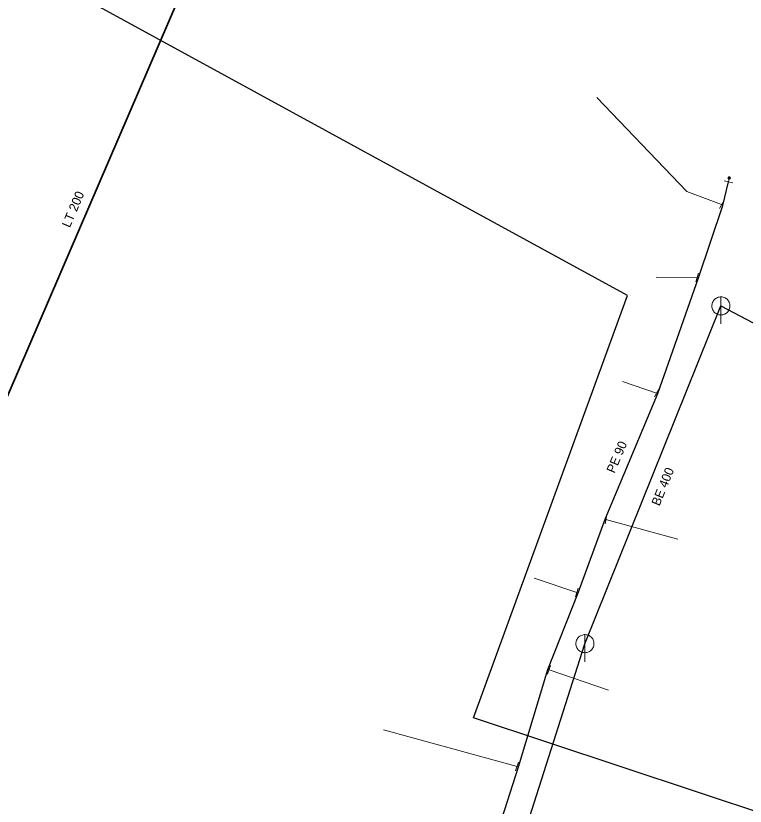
# Model space of a CAD drawing. Extents: x -659250 to -657316, y -997555 to -993684.
# Drawn here: x -658626.7 to -658546, y -994093.6 to -994006.2 of the extents above; entities that cross this region are included whole.
import ezdxf

# ---------------------------------------------------------------- set-up
doc = ezdxf.new("R2010")
doc.units = 0
doc.header["$LTSCALE"] = 0.4
doc.layers.add('1', color=7, linetype='Continuous')
for name, color, linetype, lineweight in [('13', 7, 'Continuous', 13), ('14', 7, 'Continuous', 25), ('17', 7, 'Continuous', 25), ('22', 7, 'Continuous', 13), ('34', 7, 'Continuous', 13), ('9', 7, 'Continuous', 13)]:
    doc.layers.add(name, color=color, linetype=linetype, lineweight=lineweight)

msp = doc.modelspace()

# ---------------------------------------------------------------- linework, layer by layer
at = {"layer": '13'}
for p, q in [((-658551.329, -994035.11), (-658555.879, -994035.079)), ((-658555.82, -994047.899), (-658559.6, -994046.64)), ((-658561.425, -994061.899), (-658553.46, -994064.059)), ((-658564.64, -994069.969), (-658569.379, -994068.39)), ((-658567.725, -994078.53), (-658561.149, -994080.8))]:
    msp.add_line(p, q, dxfattribs=at)
for points in [[(-658548.635, -994027.05), (-658552.48, -994025.609), (-658562.443, -994015.175)], [(-658571.265, -994089.23), (-658580.239, -994086.76), (-658586.024, -994085.167)]]:
    msp.add_lwpolyline(points, dxfattribs=at)
at = {"layer": '14', "lineweight": 13}
for p, q in [((-658547.879, -994024.539), (-658547.789, -994024.1)), ((-658548.489, -994027.129), (-658548.635, -994027.05)), ((-658551.19, -994035.149), (-658551.329, -994035.11)), ((-658555.69, -994047.969), (-658555.82, -994047.899)), ((-658561.53, -994061.879), (-658561.425, -994061.899)), ((-658564.5, -994070.01), (-658564.64, -994069.969)), ((-658567.85, -994078.489), (-658567.725, -994078.53)), ((-658571.09, -994089.289), (-658571.265, -994089.23))]:
    msp.add_line(p, q, dxfattribs=at)
at = {"layer": '14'}
for p, q in [((-658563.75, -994075.64), (-658548.71, -994038.26)), ((-658578.5, -994122), (-658563.75, -994075.64))]:
    msp.add_line(p, q, dxfattribs=at)
msp.add_lwpolyline([(-658548.71, -994038.26), (-658538.059, -994043.84), (-658522.079, -994033.039)], dxfattribs=at)
at = {"layer": '17'}
for points in [[(-658533.629, -994132.381), (-658543.176, -994094.762), (-658576.06, -994083.83), (-658559.027, -994037.098), (-658707.828, -993955.756)], [(-658582.945, -994175.84), (-658583.26, -994175.57), (-658583.69, -994175), (-658582.98, -994161.28), (-658582.379, -994139.309), (-658581.96, -994126.789), (-658580.94, -994122), (-658579.92, -994117.25), (-658576.27, -994105.41), (-658571.09, -994089.289), (-658567.85, -994078.489), (-658564.5, -994070.01), (-658561.53, -994061.879), (-658555.69, -994047.969), (-658551.19, -994035.149), (-658548.489, -994027.129), (-658547.875, -994024.539)]]:
    msp.add_lwpolyline(points, dxfattribs=at)
at = {"layer": '17', "lineweight": 35}
msp.add_lwpolyline([(-658606.489, -993999.12), (-658630.8, -994055.498), (-658631.567, -994056.124), (-658641.039, -994058.82), (-658654.85, -994061.37), (-658667.579, -994061.629), (-658691.82, -994061.09), (-658697.82, -994061.89), (-658705.28, -994063.05), (-658714.96, -994065.02), (-658748.18, -994070.859), (-658765.02, -994074.25), (-658773.51, -994075.829), (-658797.75, -994079.43), (-658815.379, -994082.92), (-658817.14, -994084.09), (-658829.09, -994095.52), (-658850.25, -994116.16), (-658876.489, -994141.66), (-658906.53, -994170.03)], dxfattribs=at)
at = {"layer": '22'}
for p, q in [((-658548.71, -994040.26), (-658548.709, -994037.26)), ((-658563.75, -994077.64), (-658563.749, -994074.64))]:
    msp.add_line(p, q, dxfattribs=at)
for points in [[(-658547.71, -994038.26), (-658547.715, -994038.151), (-658547.733, -994038.043), (-658547.763, -994037.937), (-658547.803, -994037.836), (-658547.855, -994037.739), (-658547.917, -994037.649), (-658547.989, -994037.566), (-658548.069, -994037.492), (-658548.157, -994037.426), (-658548.251, -994037.371), (-658548.351, -994037.326), (-658548.456, -994037.293), (-658548.563, -994037.271), (-658548.672, -994037.261), (-658548.782, -994037.263), (-658548.89, -994037.277), (-658548.997, -994037.302), (-658549.1, -994037.339), (-658549.198, -994037.388), (-658549.29, -994037.446), (-658549.376, -994037.515), (-658549.453, -994037.592), (-658549.522, -994037.678), (-658549.581, -994037.77), (-658549.629, -994037.868), (-658549.666, -994037.971), (-658549.692, -994038.078), (-658549.706, -994038.186), (-658549.709, -994038.296), (-658549.699, -994038.405), (-658549.678, -994038.512), (-658549.644, -994038.616), (-658549.6, -994038.716), (-658549.545, -994038.811), (-658549.479, -994038.899), (-658549.405, -994038.979), (-658549.322, -994039.051), (-658549.232, -994039.113), (-658549.136, -994039.165), (-658549.034, -994039.206), (-658548.929, -994039.236), (-658548.821, -994039.254), (-658548.711, -994039.26), (-658548.602, -994039.254), (-658548.494, -994039.236), (-658548.389, -994039.207), (-658548.287, -994039.166), (-658548.19, -994039.114), (-658548.1, -994039.052), (-658548.017, -994038.981), (-658547.942, -994038.901), (-658547.877, -994038.813), (-658547.821, -994038.719), (-658547.777, -994038.619), (-658547.743, -994038.515), (-658547.721, -994038.407), (-658547.711, -994038.298)], [(-658562.75, -994075.64), (-658562.755, -994075.531), (-658562.773, -994075.423), (-658562.803, -994075.317), (-658562.843, -994075.216), (-658562.895, -994075.119), (-658562.957, -994075.029), (-658563.029, -994074.946), (-658563.109, -994074.872), (-658563.197, -994074.806), (-658563.291, -994074.751), (-658563.391, -994074.706), (-658563.496, -994074.673), (-658563.603, -994074.651), (-658563.712, -994074.641), (-658563.822, -994074.643), (-658563.93, -994074.657), (-658564.037, -994074.682), (-658564.14, -994074.719), (-658564.238, -994074.768), (-658564.33, -994074.826), (-658564.416, -994074.895), (-658564.493, -994074.972), (-658564.562, -994075.058), (-658564.621, -994075.15), (-658564.669, -994075.248), (-658564.706, -994075.351), (-658564.732, -994075.458), (-658564.746, -994075.566), (-658564.749, -994075.676), (-658564.739, -994075.785), (-658564.718, -994075.892), (-658564.684, -994075.996), (-658564.64, -994076.096), (-658564.585, -994076.191), (-658564.519, -994076.279), (-658564.445, -994076.359), (-658564.362, -994076.431), (-658564.272, -994076.493), (-658564.176, -994076.545), (-658564.074, -994076.586), (-658563.969, -994076.616), (-658563.861, -994076.634), (-658563.751, -994076.64), (-658563.642, -994076.634), (-658563.534, -994076.616), (-658563.429, -994076.587), (-658563.327, -994076.546), (-658563.23, -994076.494), (-658563.14, -994076.432), (-658563.057, -994076.361), (-658562.982, -994076.281), (-658562.917, -994076.193), (-658562.861, -994076.099), (-658562.817, -994075.999), (-658562.783, -994075.895), (-658562.761, -994075.787), (-658562.751, -994075.678)]]:
    msp.add_lwpolyline(points, close=True, dxfattribs=at)
at = {"layer": '34'}
for p, q in [((-658548.361, -994024.423), (-658547.388, -994024.655)), ((-658548.876, -994027.488), (-658548.393, -994026.612)), ((-658551.465, -994035.59), (-658551.191, -994034.629)), ((-658556.056, -994048.339), (-658555.582, -994047.459)), ((-658561.331, -994061.407), (-658561.519, -994062.39)), ((-658564.776, -994070.449), (-658564.502, -994069.488)), ((-658567.573, -994078.053), (-658567.877, -994079.006)), ((-658571.426, -994089.703), (-658571.102, -994088.757))]:
    msp.add_line(p, q, dxfattribs=at)
at = {"layer": '9'}
for points in [[(-658547.915, -994024.1), (-658547.915, -994024.113), (-658547.913, -994024.126), (-658547.91, -994024.139), (-658547.905, -994024.151), (-658547.899, -994024.163), (-658547.892, -994024.174), (-658547.884, -994024.184), (-658547.874, -994024.194), (-658547.864, -994024.202), (-658547.853, -994024.209), (-658547.841, -994024.215), (-658547.829, -994024.22), (-658547.816, -994024.223), (-658547.803, -994024.225), (-658547.79, -994024.227), (-658547.777, -994024.226), (-658547.764, -994024.224), (-658547.751, -994024.221), (-658547.739, -994024.216), (-658547.727, -994024.21), (-658547.716, -994024.203), (-658547.706, -994024.195), (-658547.696, -994024.185), (-658547.688, -994024.175), (-658547.681, -994024.164), (-658547.675, -994024.152), (-658547.67, -994024.14), (-658547.667, -994024.127), (-658547.665, -994024.114), (-658547.663, -994024.101), (-658547.664, -994024.088), (-658547.666, -994024.075), (-658547.669, -994024.062), (-658547.674, -994024.05), (-658547.679, -994024.038), (-658547.687, -994024.027), (-658547.695, -994024.017), (-658547.705, -994024.007), (-658547.715, -994023.999), (-658547.726, -994023.992), (-658547.738, -994023.986), (-658547.75, -994023.981), (-658547.763, -994023.978), (-658547.776, -994023.976), (-658547.789, -994023.975), (-658547.802, -994023.975), (-658547.815, -994023.977), (-658547.828, -994023.98), (-658547.84, -994023.985), (-658547.852, -994023.991), (-658547.863, -994023.998), (-658547.873, -994024.006), (-658547.883, -994024.016), (-658547.891, -994024.026), (-658547.898, -994024.037), (-658547.904, -994024.049), (-658547.909, -994024.061), (-658547.912, -994024.074), (-658547.914, -994024.087)], [(-658547.895, -994024.1), (-658547.896, -994024.111), (-658547.894, -994024.122), (-658547.891, -994024.133), (-658547.887, -994024.143), (-658547.882, -994024.153), (-658547.876, -994024.162), (-658547.869, -994024.171), (-658547.861, -994024.179), (-658547.852, -994024.186), (-658547.843, -994024.192), (-658547.833, -994024.197), (-658547.823, -994024.201), (-658547.812, -994024.204), (-658547.801, -994024.207), (-658547.79, -994024.207), (-658547.779, -994024.207), (-658547.768, -994024.205), (-658547.757, -994024.202), (-658547.747, -994024.198), (-658547.737, -994024.193), (-658547.728, -994024.187), (-658547.719, -994024.18), (-658547.711, -994024.172), (-658547.704, -994024.163), (-658547.698, -994024.154), (-658547.693, -994024.144), (-658547.689, -994024.134), (-658547.686, -994024.123), (-658547.684, -994024.112), (-658547.683, -994024.101), (-658547.683, -994024.09), (-658547.684, -994024.079), (-658547.688, -994024.068), (-658547.692, -994024.058), (-658547.697, -994024.048), (-658547.703, -994024.039), (-658547.71, -994024.03), (-658547.718, -994024.022), (-658547.727, -994024.015), (-658547.736, -994024.009), (-658547.746, -994024.004), (-658547.755, -994024), (-658547.767, -994023.997), (-658547.777, -994023.995), (-658547.789, -994023.995), (-658547.8, -994023.994), (-658547.811, -994023.996), (-658547.822, -994023.999), (-658547.831, -994024.003), (-658547.842, -994024.008), (-658547.851, -994024.014), (-658547.86, -994024.021), (-658547.868, -994024.029), (-658547.875, -994024.038), (-658547.88, -994024.047), (-658547.886, -994024.057), (-658547.89, -994024.067), (-658547.893, -994024.078), (-658547.895, -994024.089)], [(-658547.876, -994024.1), (-658547.876, -994024.109), (-658547.875, -994024.118), (-658547.872, -994024.127), (-658547.869, -994024.135), (-658547.865, -994024.143), (-658547.86, -994024.151), (-658547.853, -994024.158), (-658547.848, -994024.164), (-658547.841, -994024.17), (-658547.833, -994024.175), (-658547.825, -994024.179), (-658547.817, -994024.182), (-658547.808, -994024.185), (-658547.799, -994024.186), (-658547.79, -994024.188), (-658547.781, -994024.187), (-658547.772, -994024.186), (-658547.763, -994024.183), (-658547.755, -994024.18), (-658547.747, -994024.176), (-658547.739, -994024.171), (-658547.732, -994024.165), (-658547.726, -994024.159), (-658547.72, -994024.152), (-658547.715, -994024.144), (-658547.711, -994024.136), (-658547.708, -994024.128), (-658547.705, -994024.119), (-658547.704, -994024.11), (-658547.701, -994024.101), (-658547.703, -994024.092), (-658547.704, -994024.083), (-658547.706, -994024.074), (-658547.71, -994024.066), (-658547.714, -994024.058), (-658547.719, -994024.05), (-658547.725, -994024.043), (-658547.731, -994024.037), (-658547.738, -994024.031), (-658547.746, -994024.026), (-658547.754, -994024.022), (-658547.762, -994024.019), (-658547.771, -994024.016), (-658547.78, -994024.015), (-658547.789, -994024.014), (-658547.798, -994024.014), (-658547.807, -994024.015), (-658547.816, -994024.018), (-658547.824, -994024.021), (-658547.831, -994024.025), (-658547.84, -994024.03), (-658547.847, -994024.036), (-658547.853, -994024.042), (-658547.858, -994024.049), (-658547.864, -994024.057), (-658547.868, -994024.065), (-658547.871, -994024.073), (-658547.874, -994024.082), (-658547.875, -994024.091)], [(-658547.856, -994024.1), (-658547.856, -994024.107), (-658547.855, -994024.114), (-658547.853, -994024.121), (-658547.851, -994024.127), (-658547.848, -994024.133), (-658547.844, -994024.139), (-658547.84, -994024.145), (-658547.835, -994024.15), (-658547.829, -994024.154), (-658547.823, -994024.158), (-658547.817, -994024.161), (-658547.811, -994024.164), (-658547.804, -994024.165), (-658547.797, -994024.168), (-658547.79, -994024.168), (-658547.782, -994024.168), (-658547.776, -994024.166), (-658547.769, -994024.165), (-658547.763, -994024.162), (-658547.755, -994024.159), (-658547.751, -994024.155), (-658547.745, -994024.151), (-658547.74, -994024.146), (-658547.736, -994024.14), (-658547.732, -994024.134), (-658547.728, -994024.128), (-658547.726, -994024.122), (-658547.724, -994024.115), (-658547.723, -994024.108), (-658547.722, -994024.101), (-658547.722, -994024.094), (-658547.723, -994024.087), (-658547.725, -994024.08), (-658547.728, -994024.074), (-658547.731, -994024.067), (-658547.735, -994024.062), (-658547.739, -994024.056), (-658547.744, -994024.051), (-658547.75, -994024.047), (-658547.755, -994024.043), (-658547.762, -994024.04), (-658547.768, -994024.037), (-658547.775, -994024.035), (-658547.782, -994024.034), (-658547.789, -994024.034), (-658547.796, -994024.034), (-658547.803, -994024.034), (-658547.809, -994024.036), (-658547.816, -994024.039), (-658547.822, -994024.042), (-658547.828, -994024.046), (-658547.834, -994024.05), (-658547.839, -994024.055), (-658547.843, -994024.061), (-658547.847, -994024.066), (-658547.85, -994024.073), (-658547.853, -994024.079), (-658547.853, -994024.086), (-658547.856, -994024.093)], [(-658547.836, -994024.1), (-658547.836, -994024.105), (-658547.836, -994024.11), (-658547.835, -994024.115), (-658547.833, -994024.119), (-658547.831, -994024.124), (-658547.828, -994024.128), (-658547.825, -994024.131), (-658547.821, -994024.135), (-658547.818, -994024.138), (-658547.814, -994024.141), (-658547.809, -994024.143), (-658547.804, -994024.145), (-658547.8, -994024.146), (-658547.795, -994024.148), (-658547.79, -994024.148), (-658547.785, -994024.148), (-658547.78, -994024.147), (-658547.775, -994024.146), (-658547.771, -994024.144), (-658547.766, -994024.142), (-658547.762, -994024.139), (-658547.758, -994024.136), (-658547.755, -994024.132), (-658547.752, -994024.129), (-658547.749, -994024.125), (-658547.747, -994024.12), (-658547.745, -994024.116), (-658547.744, -994024.111), (-658547.743, -994024.106), (-658547.742, -994024.101), (-658547.742, -994024.096), (-658547.743, -994024.091), (-658547.744, -994024.086), (-658547.746, -994024.082), (-658547.748, -994024.077), (-658547.751, -994024.073), (-658547.754, -994024.069), (-658547.757, -994024.066), (-658547.761, -994024.063), (-658547.765, -994024.06), (-658547.77, -994024.058), (-658547.774, -994024.056), (-658547.779, -994024.055), (-658547.784, -994024.054), (-658547.789, -994024.054), (-658547.794, -994024.054), (-658547.799, -994024.055), (-658547.804, -994024.055), (-658547.808, -994024.057), (-658547.813, -994024.059), (-658547.817, -994024.062), (-658547.82, -994024.065), (-658547.824, -994024.068), (-658547.826, -994024.072), (-658547.83, -994024.076), (-658547.831, -994024.081), (-658547.834, -994024.085), (-658547.835, -994024.09), (-658547.836, -994024.095)], [(-658547.816, -994024.1), (-658547.816, -994024.103), (-658547.817, -994024.106), (-658547.816, -994024.108), (-658547.815, -994024.111), (-658547.814, -994024.114), (-658547.812, -994024.116), (-658547.809, -994024.118), (-658547.808, -994024.12), (-658547.806, -994024.122), (-658547.804, -994024.124), (-658547.801, -994024.126), (-658547.798, -994024.127), (-658547.796, -994024.127), (-658547.793, -994024.128), (-658547.79, -994024.128), (-658547.787, -994024.128), (-658547.784, -994024.128), (-658547.781, -994024.127), (-658547.779, -994024.126), (-658547.776, -994024.125), (-658547.774, -994024.123), (-658547.771, -994024.121), (-658547.769, -994024.119), (-658547.768, -994024.117), (-658547.766, -994024.115), (-658547.765, -994024.112), (-658547.763, -994024.109), (-658547.763, -994024.107), (-658547.762, -994024.104), (-658547.761, -994024.101), (-658547.762, -994024.098), (-658547.762, -994024.095), (-658547.763, -994024.092), (-658547.764, -994024.09), (-658547.765, -994024.087), (-658547.767, -994024.085), (-658547.768, -994024.082), (-658547.77, -994024.08), (-658547.773, -994024.079), (-658547.775, -994024.077), (-658547.777, -994024.076), (-658547.78, -994024.075), (-658547.782, -994024.074), (-658547.786, -994024.074), (-658547.789, -994024.073), (-658547.792, -994024.074), (-658547.795, -994024.073), (-658547.797, -994024.075), (-658547.8, -994024.075), (-658547.803, -994024.076), (-658547.804, -994024.078), (-658547.807, -994024.079), (-658547.809, -994024.081), (-658547.811, -994024.084), (-658547.813, -994024.086), (-658547.814, -994024.089), (-658547.815, -994024.091), (-658547.816, -994024.094), (-658547.816, -994024.097)], [(-658547.797, -994024.1), (-658547.797, -994024.102), (-658547.797, -994024.102), (-658547.796, -994024.102), (-658547.796, -994024.104), (-658547.797, -994024.105), (-658547.795, -994024.105), (-658547.795, -994024.105), (-658547.795, -994024.107), (-658547.795, -994024.107), (-658547.794, -994024.108), (-658547.792, -994024.108), (-658547.792, -994024.108), (-658547.792, -994024.109), (-658547.79, -994024.109), (-658547.79, -994024.109), (-658547.789, -994024.109), (-658547.788, -994024.109), (-658547.788, -994024.108), (-658547.787, -994024.108), (-658547.785, -994024.108), (-658547.785, -994024.107), (-658547.785, -994024.107), (-658547.784, -994024.106), (-658547.784, -994024.106), (-658547.782, -994024.105), (-658547.782, -994024.104), (-658547.781, -994024.103), (-658547.781, -994024.103), (-658547.781, -994024.102), (-658547.781, -994024.101), (-658547.781, -994024.1), (-658547.781, -994024.099), (-658547.781, -994024.099), (-658547.782, -994024.098), (-658547.782, -994024.097), (-658547.782, -994024.096), (-658547.782, -994024.096), (-658547.784, -994024.095), (-658547.784, -994024.095), (-658547.785, -994024.094), (-658547.786, -994024.094), (-658547.787, -994024.093), (-658547.787, -994024.093), (-658547.788, -994024.093), (-658547.789, -994024.093), (-658547.79, -994024.093), (-658547.791, -994024.093), (-658547.791, -994024.093), (-658547.792, -994024.094), (-658547.793, -994024.093), (-658547.794, -994024.095), (-658547.794, -994024.095), (-658547.795, -994024.095), (-658547.795, -994024.095), (-658547.796, -994024.097), (-658547.796, -994024.098), (-658547.796, -994024.099), (-658547.797, -994024.099), (-658547.797, -994024.1)]]:
    msp.add_lwpolyline(points, close=True, dxfattribs=at)

# ---------------------------------------------------------------- texts
at = {"layer": '1'}
for s, rotation, p in [('LT 200', 67, (-658620.736, -994029.672)), ('PE 90 ', 67, (-658560.485, -994056.848)), ('BE 400', 68, (-658555.507, -994060.473))]:
    msp.add_text(s, height=1, rotation=rotation, dxfattribs=at).set_placement(p)

doc.saveas('drawing.dxf')
